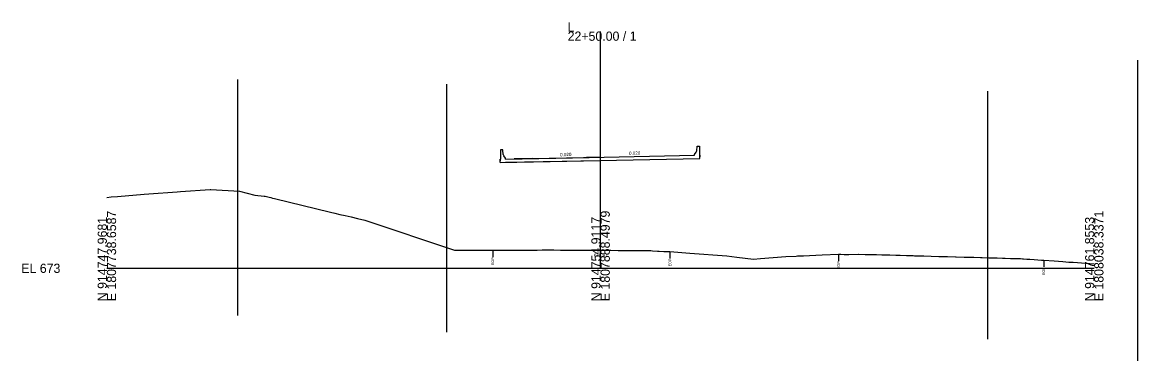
# Model space of a CAD drawing. Extents: x -26 to 1352, y -510 to 9596.
# Drawn here: x -25.7 to 313.2, y 8472 to 8574.6 of the extents above; entities that cross this region are included whole.
import ezdxf

# ---------------------------------------------------------------- set-up
doc = ezdxf.new("R2010")
doc.units = 0
for name, color, linetype in [('Default', 7, 'Continuous'), ('Exist Cross Section Cell', 7, 'Continuous'), ('Exist XS Center Line Elevation Label', 7, 'Continuous'), ('Exist XS Ground Line', 7, 'Continuous'), ('Old_Level_10', 7, 'Continuous'), ('Prop XS Bridge', 7, 'Continuous'), ('Prop XS Exc Vertical Line 1', 7, 'Continuous'), ('Prop XS Exc Vertical Line 2', 7, 'Continuous'), ('Prop XS Exc Vertical Line 3', 7, 'Continuous'), ('Prop XS Exc Vertical Line 4', 7, 'Continuous'), ('Prop XS SE Text', 7, 'Continuous')]:
    doc.layers.add(name, color=color, linetype=linetype)

msp = doc.modelspace()

# ---------------------------------------------------------------- linework, layer by layer
at = {"layer": 'Default'}
for p, q in [((179.2, 8535.66), (179.35, 8537.05)), ((179.35, 8537.05), (179.39, 8537.09)), ((179.39, 8537.09), (180.02, 8537.09)), ((180.02, 8537.09), (180.05, 8537.06)), ((180.05, 8537.06), (180.05, 8534.31)), ((119.46, 8532.13), (180.18, 8533.34)), ((119.63, 8535.94), (119.59, 8535.91)), ((119.59, 8535.91), (119.59, 8533.16)), ((120.26, 8535.94), (119.63, 8535.94)), ((120.29, 8535.9), (120.26, 8535.94)), ((120.44, 8534.51), (120.29, 8535.9)), ((121.07, 8533.42), (120.59, 8534.1)), ((121.07, 8533.16), (146.57, 8533.67)), ((121.07, 8533.16), (121.07, 8533.42)), ((150, 8533.74), (145.71, 8533.65)), ((146.57, 8533.67), (178.57, 8534.31)), ((178.57, 8534.57), (179.05, 8535.25)), ((178.57, 8534.31), (178.57, 8534.57)), ((180.05, 8534.31), (180.11, 8534.31)), ((180.11, 8534.31), (180.18, 8534.24)), ((180.18, 8534.24), (180.18, 8533.79)), ((180.18, 8533.34), (180.18, 8534.24)), ((119.53, 8533.16), (119.46, 8533.09)), ((119.46, 8532.13), (119.46, 8533.09)), ((119.46, 8533.09), (119.46, 8532.64)), ((119.59, 8533.16), (119.53, 8533.16)), ((121.09, 8532.16), (149.82, 8532.73))]:
    msp.add_line(p, q, dxfattribs=at)
for centre, start, end in [((121.3, 8534.6), 186.0111, 214.9913), ((178.34, 8535.75), 325.0087, 353.9889)]:
    msp.add_arc(centre, 0.869, start, end, dxfattribs=at)
at = {"layer": 'Exist Cross Section Cell'}
for p, q in [((150, 8500), (150, 8571.85)), ((0, 8500), (150, 8500)), ((150, 8500), (300, 8500))]:
    msp.add_line(p, q, dxfattribs=at)
at = {"layer": 'Exist XS Ground Line'}
msp.add_lwpolyline([(0, 8521.52), (1.34, 8521.67), (3.23, 8521.82), (11.35, 8522.53), (12.79, 8522.59), (21.36, 8523.23), (22.36, 8523.26), (31.37, 8523.95), (31.56, 8523.94), (40.32, 8523.4), (44.93, 8522.15), (47.79, 8521.92), (48.12, 8521.85), (48.48, 8521.76), (48.87, 8521.67), (49.29, 8521.57), (49.77, 8521.46), (50.3, 8521.33), (50.88, 8521.19), (67.94, 8517.03), (69.3, 8516.72), (70.78, 8516.37), (72.4, 8515.99), (74.19, 8515.57), (76.16, 8515.11), (78.36, 8514.59), (105.66, 8505.55), (106.32, 8505.54), (106.88, 8505.53), (107.72, 8505.53), (108.7, 8505.49), (109.86, 8505.47), (111.24, 8505.5), (112.92, 8505.5), (115.01, 8505.48), (117.25, 8505.46), (117.54, 8505.46), (117.96, 8505.47), (120.29, 8505.48), (121.61, 8505.5), (122.79, 8505.5), (124.25, 8505.5), (125.29, 8505.5), (126.23, 8505.51), (127.79, 8505.51), (128.63, 8505.53), (130.31, 8505.52), (130.73, 8505.53), (132.23, 8505.58), (132.36, 8505.58), (134.74, 8505.56), (135.28, 8505.56), (135.77, 8505.56), (137.81, 8505.54), (138.22, 8505.54), (140.32, 8505.53), (142.6, 8505.51), (142.8, 8505.51), (145.25, 8505.48), (145.3, 8505.48), (145.38, 8505.48), (146.39, 8505.48), (147.75, 8505.47), (147.82, 8505.47), (147.97, 8505.47), (148.52, 8505.47), (149.97, 8505.47), (150, 8505.47), (150.34, 8505.47), (152.57, 8505.45), (152.81, 8505.45), (153.11, 8505.45), (155.33, 8505.44), (155.72, 8505.44), (157.84, 8505.42), (158.36, 8505.41), (160.33, 8505.39), (160.99, 8505.38), (162.84, 8505.36), (164.4, 8505.36), (164.94, 8505.35), (165.28, 8505.35), (165.81, 8505.3), (167.26, 8505.24), (167.82, 8505.19), (169.26, 8505.14), (170.24, 8505.1), (171.08, 8505.07), (177.16, 8504.6), (188.38, 8503.73), (191.43, 8503.37), (196.45, 8502.76), (198.64, 8502.96), (206.29, 8503.58), (209.39, 8503.71), (209.88, 8503.73), (210.57, 8503.76), (211.63, 8503.8), (213.44, 8503.88), (217.29, 8504.04), (222.32, 8504.26), (222.98, 8504.25), (224, 8504.23), (225.4, 8504.22), (228.27, 8504.29), (228.32, 8504.29), (228.34, 8504.29), (228.39, 8504.29), (230.4, 8504.23), (231.82, 8504.2), (232.9, 8504.17), (233.87, 8504.15), (235.42, 8504.11), (237.11, 8504.07), (237.92, 8504.05), (239.72, 8504), (240.41, 8503.98), (241.04, 8503.96), (242.91, 8503.91), (243.78, 8503.88), (244.98, 8503.85), (244.99, 8503.85), (245.41, 8503.83), (245.83, 8503.82), (247.92, 8503.76), (248.23, 8503.75), (250.46, 8503.68), (252.81, 8503.62), (252.91, 8503.62), (254.5, 8503.57), (255.43, 8503.54), (257.84, 8503.47), (257.94, 8503.47), (258.05, 8503.47), (260.46, 8503.39), (260.79, 8503.39), (261.16, 8503.37), (262.81, 8503.34), (263.37, 8503.33), (265.4, 8503.27), (265.9, 8503.26), (267.94, 8503.21), (268.57, 8503.19), (270.48, 8503.14), (272.14, 8503.09), (272.94, 8503.07), (274.55, 8503.02), (275.46, 8502.99), (276.57, 8502.96), (277.54, 8502.93), (278.17, 8502.91), (278.48, 8502.89), (279.53, 8502.79), (280.42, 8502.73), (281.72, 8502.62), (282.86, 8502.56), (283.96, 8502.49), (284.65, 8502.45), (287.82, 8502.22), (290.49, 8502.02), (292.3, 8501.89), (293.6, 8501.81), (300, 8501.32)], dxfattribs=at)
at = {"layer": 'Old_Level_10'}
for p, q in [((117.25, 8505.46), (117.25, 8503.41)), ((171.08, 8505.07), (171.08, 8503.02)), ((222.32, 8504.26), (222.32, 8502.21)), ((284.65, 8502.45), (284.65, 8500.4))]:
    msp.add_line(p, q, dxfattribs=at)
at = {"layer": 'Prop XS Bridge'}
for q in [(123.75, 8533.21), (150, 8533.74)]:
    msp.add_line((129.25, 8533.32), q, dxfattribs=at)
at = {"layer": 'Prop XS Exc Vertical Line 1'}
msp.add_line((39.79, 8485.64), (39.79, 8557.3), dxfattribs=at)
at = {"layer": 'Prop XS Exc Vertical Line 2'}
msp.add_line((103.25, 8480.63), (103.25, 8555.87), dxfattribs=at)
at = {"layer": 'Prop XS Exc Vertical Line 3'}
msp.add_line((267.71, 8478.48), (267.71, 8553.71), dxfattribs=at)
at = {"layer": 'Prop XS Exc Vertical Line 4'}
msp.add_line((313.19, 8471.96), (313.19, 8563.16), dxfattribs=at)

# ---------------------------------------------------------------- texts
at = {"layer": 'Exist Cross Section Cell'}
for s, p in [('L', (140, 8571.85)), ('22+50.00 / 1', (140, 8569.05)), ('EL 673', (-26, 8498.6))]:
    msp.add_text(s, height=2.8, dxfattribs=at).set_placement(p)
for s, p in [('E 1807738.6587', (2.8, 8490)), ('E 1807888.4979', (152.8, 8490)), ('E 1808038.3371', (302.8, 8490)), ('N 914747.9681', (0, 8490)), ('N 914754.9117', (150, 8490)), ('N 914761.8553', (300, 8490))]:
    msp.add_text(s, height=2.8, rotation=90, dxfattribs=at).set_placement(p)
at = {"layer": 'Exist XS Center Line Elevation Label'}
msp.add_text('678.47', height=1, dxfattribs=at).set_placement((147.96, 8503.47))
at = {"layer": 'Old_Level_10'}
for p in [(117.64, 8501.02), (171.47, 8500.62), (222.71, 8499.81), (285.04, 8498)]:
    msp.add_text('EOP', height=0.787, rotation=90, dxfattribs=at).set_placement(p)
at = {"layer": 'Prop XS SE Text'}
for p in [(137.7, 8533.99), (158.63, 8534.41)]:
    msp.add_text('0.020', height=1, rotation=1.1458, dxfattribs=at).set_placement(p)

doc.saveas('drawing.dxf')
